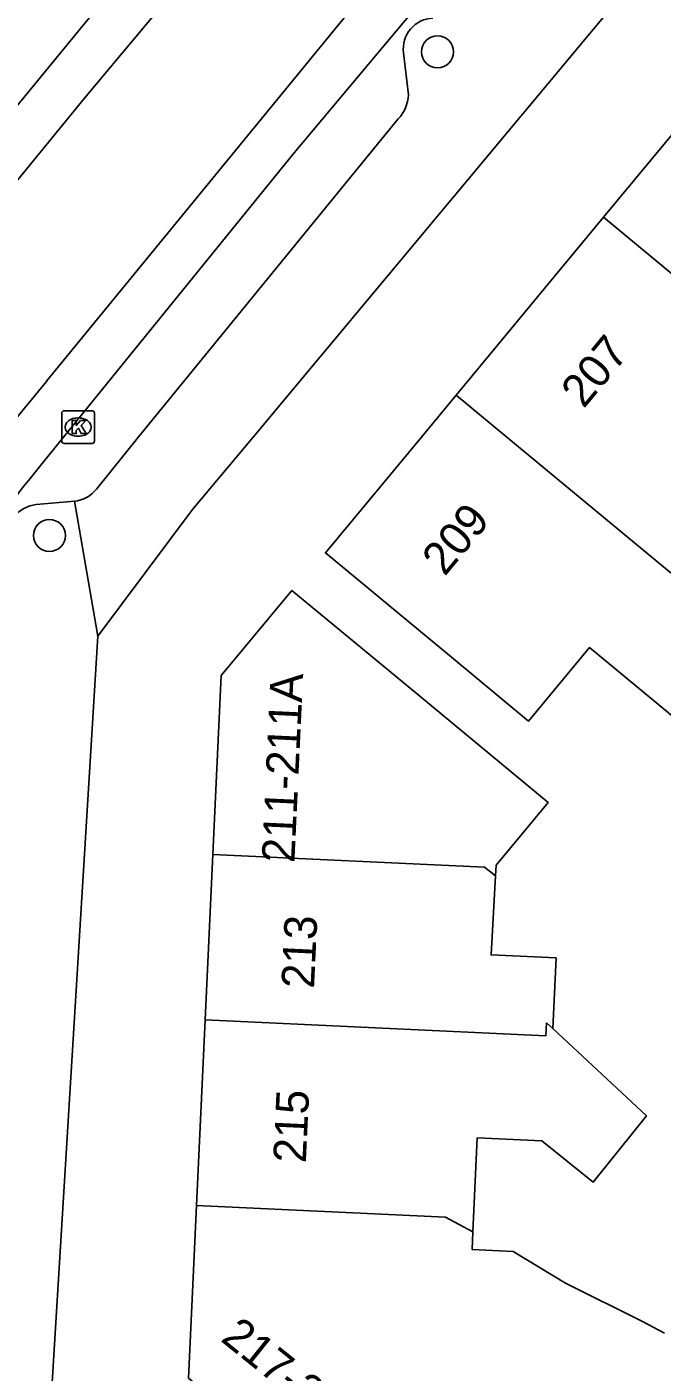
# Model space of a CAD drawing. Extents: x 160158 to 160921, y 381517 to 382041.
# Drawn here: x 160559 to 160578.42, y 381721.4 to 381762.55 of the extents above; entities that cross this region are included whole.
import ezdxf

# ---------------------------------------------------------------- set-up
doc = ezdxf.new("R2010")
doc.units = 0
for name, color, linetype in [('IMGEO_Boom', 7, 'Continuous'), ('IMGEO_Kolk', 7, 'Continuous'), ('IMGEO_Pand', 7, 'Continuous'), ('IMGEO_Pand_nummerreeks', 7, 'Continuous'), ('IMGEO_Rijbaan_lokaal_gesloten', 7, 'Continuous'), ('IMGEO_Voetpad_open', 7, 'Continuous')]:
    doc.layers.add(name, color=color, linetype=linetype)

msp = doc.modelspace()

# ---------------------------------------------------------------- linework, layer by layer
at = {"layer": 'IMGEO_Boom'}
for centre in [(160571.553, 381761.785), (160559.686, 381746.988)]:
    msp.add_circle(centre, 0.489, dxfattribs=at)
at = {"layer": 'IMGEO_Kolk'}
for p, q in [((160560.063, 381749.878), (160560.063, 381750.73)), ((160560.138, 381750.804), (160560.99, 381750.804)), ((160560.551, 381750.584), (160560.576, 381750.584)), ((160561.064, 381750.73), (160561.064, 381749.878)), ((160560.99, 381749.804), (160560.138, 381749.804)), ((160560.574, 381750.024), (160560.549, 381750.024))]:
    msp.add_line(p, q, dxfattribs=at)
for points in [[(160560.063, 381749.878), (160560.063, 381750.73)], [(160560.138, 381750.804), (160560.99, 381750.804)], [(160561.064, 381750.73), (160561.064, 381749.878)], [(160560.384, 381750.504), (160560.507, 381750.504), (160560.507, 381750.353), (160560.637, 381750.504), (160560.801, 381750.504), (160560.655, 381750.353), (160560.808, 381750.104), (160560.656, 381750.104), (160560.571, 381750.268), (160560.507, 381750.201), (160560.507, 381750.104), (160560.384, 381750.104), (160560.384, 381750.504)], [(160560.99, 381749.804), (160560.138, 381749.804)]]:
    msp.add_lwpolyline(points, dxfattribs=at)
for centre, start, end in [((160560.14, 381750.728), 91.552, 178.448), ((160560.14, 381750.728), 91.552, 178.448), ((160560.988, 381750.728), 1.552, 88.448), ((160560.988, 381750.728), 1.552, 88.448), ((160560.14, 381749.88), 181.552, 268.448), ((160560.14, 381749.88), 181.552, 268.448), ((160560.988, 381749.88), 271.552, 358.448), ((160560.988, 381749.88), 271.552, 358.448)]:
    msp.add_arc(centre, 0.0765, start, end, dxfattribs=at)
for centre, major_axis, ratio, start_param, end_param in [((160560.55, 381750.304), (-0.387, 0.002), 0.722429, 4.712389, 7.853982), ((160560.575, 381750.304), (-0.39, 0.002), 0.717154, 1.570796, 4.712389)]:
    msp.add_ellipse(centre, major_axis=major_axis, ratio=ratio, start_param=start_param, end_param=end_param, dxfattribs=at)
at = {"layer": 'IMGEO_Pand'}
for points in [[(160576.632, 381756.722), (160579.972, 381760.755)], [(160576.632, 381756.722), (160572.125, 381751.28)], [(160582.827, 381751.583), (160582.646, 381751.741), (160576.632, 381756.722)], [(160582.629, 381742.571), (160580.503, 381740.004), (160576.203, 381743.565), (160574.337, 381741.312), (160571.979, 381743.266), (160568.128, 381746.455), (160571.065, 381750), (160572.125, 381751.28)], [(160572.125, 381751.28), (160573.671, 381750), (160582.428, 381742.749), (160582.629, 381742.571)], [(160573.328, 381736.577), (160573.347, 381736.905), (160574.934, 381738.82), (160570.952, 381742.119), (160567.102, 381745.309), (160564.942, 381742.702), (160564.686, 381737.226)], [(160564.686, 381737.226), (160564.449, 381732.172)], [(160564.686, 381737.226), (160572.989, 381736.838), (160573.328, 381736.577)], [(160575.08, 381731.91), (160575.181, 381734.066), (160573.191, 381734.159), (160573.328, 381736.577)], [(160564.449, 381732.172), (160564.183, 381726.487)], [(160575.08, 381731.91), (160574.889, 381732.079), (160574.871, 381731.685), (160564.449, 381732.172)], [(160572.635, 381725.69), (160572.77, 381728.566), (160574.743, 381728.474), (160576.315, 381727.209), (160577.944, 381729.232), (160575.08, 381731.91)], [(160564.183, 381726.487), (160563.936, 381721.212), (160573.979, 381713.128)], [(160572.635, 381725.69), (160571.801, 381726.131), (160564.183, 381726.487)], [(160578.499, 381722.589), (160577.825, 381722.945), (160575.47, 381724.12), (160573.871, 381725.087), (160572.609, 381725.146), (160572.635, 381725.69)]]:
    msp.add_lwpolyline(points, dxfattribs=at)
at = {"layer": 'IMGEO_Rijbaan_lokaal_gesloten'}
for points in [[(160556.164, 381754.68), (160558.112, 381757.129), (160560.755, 381760.365), (160581.539, 381785.212), (160597.19, 381803.934)], [(160600.729, 381800.991), (160582.713, 381779.526), (160568.843, 381763.002), (160559.601, 381751.709)], [(160559.501, 381749.238), (160560.113, 381750), (160567.175, 381758.693), (160571.401, 381763.753), (160601.731, 381800.097)], [(160556.569, 381757.556), (160561.758, 381763.877), (160562.011, 381764.214)]]:
    msp.add_lwpolyline(points, dxfattribs=at)
for centre, radius, start, end in [((160632.422, 381691.188), 94.687, 140.2702, 153.23003), ((160621.002, 381699.491), 79.102, 141.03142, 148.50079)]:
    msp.add_arc(centre, radius, start, end, dxfattribs=at)
at = {"layer": 'IMGEO_Voetpad_open'}
for points in [[(160561.169, 381743.908), (160564.062, 381747.78), (160565.914, 381750), (160580.313, 381767.268)], [(160570.513, 381761.754), (160570.666, 381760.463)], [(160570.352, 381759.732), (160562.416, 381750.014), (160561.124, 381748.403)], [(160560.449, 381748.035), (160559.284, 381747.937)], [(160560.449, 381748.035), (160561.169, 381743.908)], [(160571.401, 381709.981), (160559.681, 381719.582), (160561.169, 381743.908)]]:
    msp.add_lwpolyline(points, dxfattribs=at)
for centre, radius, start, end in [((160571.462, 381761.864), 0.956, 93.265, 186.5962), ((160569.511, 381760.526), 1.156, 316.6325, 356.8757), ((160560.333, 381749.052), 1.023, 276.5351, 320.662), ((160559.408, 381746.901), 1.044, 96.8317, 183.0635)]:
    msp.add_arc(centre, radius, start, end, dxfattribs=at)

# ---------------------------------------------------------------- texts
at = {"layer": 'IMGEO_Pand_nummerreeks'}
for s, rotation, p in [('207', 50.3696, (160576.026, 381750.847)), ('209', 50.3615, (160571.774, 381745.715)), ('211-211A', 87.3245, (160567.177, 381736.963)), ('213', 87.3186, (160567.777, 381733.117)), ('215', 87.3186, (160567.527, 381727.779)), ('217-217A', 321.1707, (160564.891, 381722.368))]:
    msp.add_text(s, height=1, rotation=rotation, dxfattribs=at).set_placement(p)

doc.saveas('drawing.dxf')
